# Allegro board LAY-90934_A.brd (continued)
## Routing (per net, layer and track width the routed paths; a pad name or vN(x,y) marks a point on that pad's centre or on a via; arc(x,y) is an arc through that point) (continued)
GND_CHASSIS: length 21.1
  TOP w0.635: J9.SH1 81.67,14.22 C174.2 R361.2
  BOTTOM w0.635: J9.SH2 J9.SH1
VBUS1_DET_3V3: length 10.5
  TOP w0.086: 90.93,57.91 90.99,57.86 90.99,56.73 90.99,56.73 90.99,56.58 U1.B3
  TOP w0.254: 90.93,57.91 90.93,59.06 88.01,61.98 85.23,61.98 R113.1
VBUS_DBG: length 14.7
  TOP w0.254: J11.A9 15.73,6.02 J11.B4 ; L13.1 10.83,8.55 TVS3.2 12.1,8.38 12.57,8.38 13.23,7.73 J11.A4 13.23,6.02 J11.B9
  BOTTOM w0.381: J11.B4 16.26,6.55 16.26,8.51 15.62,9.14 13.84,9.14 13.28,8.58 J11.B9
VBUS_IN: length 8
  TOP w0.254: U45.A1 U45.B1 U45.C1 U45.D1 ; U39.23 v1(46.76,25.27)
  TOP w0.381: R283.1 v1(44.45,25.01)
  L3_PWR w0.381: v1(44.45,25.01) 44.71,25.27 v1(46.76,25.27) 48.28,23.75 v3(48.89,23.75)
  vias: v3(48.89,22.86) v3(49.66,23.75) v3(49.66,22.86)
VBUS_OVLO_TH: length 3.4
  TOP w0.086: U45.B3 66.79,19.94 v1(67.56,20.71) R311.1 R313.2
VBUS_USB_DBG: length 7.3
  TOP w0.381: U50.3 10.5,13.55 v1(10.54,13.59) C177.1 C184.1 C189.1 ; U50.1 11.21,11.65 C189.1 ; C189.1 11.3,11.05 10.67,10.41 L13.2
VCC_ANA_1V8: length 9.3
  TOP w0.254: v2(93.23,54.86) 93.21,54.83 U1.E6 ; v2(93.19,50.84) 93.21,50.83 U1.N8 ; U1.L12 v2(95.73,52.32) ; U1.F12 v2(95.26,54.33)
  L2_GND w0.203: v2(95.26,54.33) 95.26,53.33 95.73,52.86 v2(95.73,52.32)
  L2_GND w0.254: v2(93.19,50.84) 94.41,50.84 94.74,51.18 94.74,51.69 95.37,52.32 v2(95.73,52.32)
  BOTTOM w0.254: C145.1 95.83,54.37 95.3,54.37 v2(95.26,54.33) ; C146.1 95.74,52.32 v2(95.73,52.32) ; v2(93.23,54.86) 93.25,54.88 C144.1
  vias: v1(31.24,44.58) v1(31.5,45.21) v1(32.13,44.58) v1(32.51,45.21) v1(33.02,44.58)
VCC_FT_1V8: length 26.8
  TOP w0.254: U28.64 4.32,29.02 v1(4.25,29.08) ; v1(12.83,37.34) 12.8,37.37 U28.37 ; U28.12 12.8,28.29 v1(12.83,28.32)
  BOTTOM w0.381: C261.1 10.72,36.58 L15.1 ; C261.1 12.86,37.31 v1(12.83,37.34) ; C261.1 12.86,29.12 C287.1 ; C287.1 C290.1 v1(4.25,29.08) ; C287.1 v1(12.83,28.32)
VCC_FT_3V3: length 257.7
  TOP w0.254: R112.1 v1(28.57,62.48) ; R252.2 v1(20.69,33.66) R255.2 ; U28.56 v1(6.35,33.02) ; U18.8 16.5,49.42 C67.1 ; v1(15.56,30.48) 15.59,30.52 U28.20 ; v1(5.01,18.16) 5.01,17.59 R333.1 ; v1(17.34,45.72) 17.39,45.66 U21.2 ; v1(4.19,36.2) 4.37,36.02 U28.50 ; R219.2 v1(12.19,44.19) ; U17.15 28.25,58.24 v1(27.94,58.55) ; v1(4.32,45.85) R198.1 ; C64.1 19.74,49.35 U21.15 ; R86.1 v1(42.42,66.68) ; R103.1 v1(28.57,63.5) ; R60.1 v1(38.73,69.6) ; U28.42 v1(10.3,37.22) ; C50.1 45.9,61.41 U16.15 ; v1(4.32,43.05) R221.1 ; v1(2.67,18.16) 2.42,18.16 2.17,17.91 R332.1 ; R282.1 v1(15.61,25.4) ; v1(4.32,51.44) R172.1 ; v1(4.32,48.64) R187.1 ; v1(15.75,35.94) 15.82,36.02 U28.31 ; R154.1 v1(14.35,55.37) ; R206.1 v1(13.58,44.45) ; C46.1 41.4,64.39 U14.6 ; R296.1 v1(4.32,24) ; U13.21 v1(41.15,70.1) ; R226.2 v1(10.66,41.54) ; R38.1 v1(38.73,72.64)
  TOP w0.381: v1(52.07,72.77) 54.1,72.77 55.37,71.5 55.37,70.23 v1(56.13,69.47) ; U17.2 25.09,55.32 C58.1 v1(25.02,54.48) ; C52.1 v1(27.94,58.55) ; C64.1 v1(18.67,49.66) ; 10.16,15.37 v1(9.14,15.37) ; v1(36.32,28.83) v1(34.55,28.83) 33.66,28.83 v1(32.26,30.23) 32.26,31.88 33.2,32.82 v1(34.04,32.82) ; v1(47.51,70.49) 47.5,70.5 C31.1 ; U16.2 42.74,58.62 C54.1 v1(42.67,57.79) ; R115.2 v1(43.31,62.61) ; U42.6 v1(5.01,18.16) ; v1(50.55,73.91) 50.55,84.33 50.93,84.71 v1(81.03,84.71) ; v1(62.74,61.21) 62.55,61.02 58.74,61.02 57.78,61.98 v1(50.04,61.98) ; v1(5.05,12.45) C188.1 5.08,11.65 U50.5 ; D18.A v1(22.73,35.56) ; TP160.1 v1(5.84,14.48) ; R180.2 v1(18.67,50.54) ; v1(17.27,48.39) C71.1 C67.1 v1(17.27,49.4) ; R195.2 v1(14.99,47.37) ; R120.2 v1(41.15,60.58) ; v1(41.02,63.75) C46.1 ; R145.2 v1(23.5,57.28) ; v1(44.83,61.72) C50.1 ; R124.2 v1(26.92,60.83)
  BOTTOM w0.203: U60.2 56.44,69.78 v1(56.13,69.47) ; U63.3 63.05,61.52 v1(62.74,61.21)
  BOTTOM w0.254: v1(50.55,65.09) R414.1 ; U64.15 36.5,30.57 36.32,30.39 C284.1 ; R413.1 v1(51.56,65.09) ; v1(5.01,18.16) 4.48,17.62 3.2,17.62 v1(2.67,18.16) ; U61.8 52.06,72.76 v1(52.07,72.77) ; U64.2 v1(34.04,32.82) ; U65.1 20.07,28.91 v1(20.07,28.45) ; R415.1 v1(52.58,65.09) ; U62.8 v1(47.51,70.49)
  BOTTOM w0.381: v1(5.01,18.16) 5.01,18.86 C311.1 ; C225.1 C229.1 41.15,70.1 v1(41.15,70.1) ; v1(56.13,69.47) C230.1 C231.1 ; v1(20.07,28.45) C299.1 C300.1 ; v1(10.3,37.22) 10.29,37.24 C258.1 ; C223.1 52.07,73.79 v1(52.07,72.77) ; v1(21.91,33.02) 26.42,33.02 27.18,32.26 30.35,32.26 31.74,30.87 R464.2 v1(32.26,30.23) ; v1(15.61,25.4) 14.98,24.77 L16.1 12.83,25.09 v1(12.83,25.53) ; v1(15.75,35.94) C263.1 ; v1(17.34,45.72) 17.46,45.85 C240.1 ; U68.5 132.6,47.1 132.08,47.63 C318.1 132.08,50.29 131.7,50.67 128.14,50.67 127.32,51.5 127.32,58.86 127.95,59.5 127.95,63.06 132.27,67.37 132.27,73.98 124.84,81.41 102.87,81.41 99.57,84.71 v1(81.03,84.71) ; v1(34.04,32.82) 33.96,32.89 C272.1 ; C282.1 v1(15.56,30.48) ; 4.95,36.32 4.32,36.32 v1(4.19,36.2) ; C236.1 C235.1 v1(62.74,61.21) ; R470.2 v1(34.55,28.83) ; L17.1 5.09,24.77 v1(4.32,24) ; v1(6.35,33.02) 6.35,33.02 C273.1 ; v1(36.32,28.83) C284.1
VCCO_5V: length 3.7
  TOP w0.254: U39.21 v1(47.76,25.4)
  BOTTOM w0.254: R472.1 C304.1 47.12,24.76 v1(47.76,25.4)
VDD_1P8: length 101.5
  TOP w0.203: v1(54.36,58.93) 54.17,59.12 51.75,59.12 R132.1 ; v1(44.96,41.4) 44.96,42.16 45.46,42.67 U23.29 ; R182.1 v1(21.46,51.18) ; 37.59,45.21 37.02,45.78 37.02,46.42 36.58,46.86 31.12,46.86 29.65,48.32 29.65,49.47 R184.1 ; TP131.1 65.15,32.13 65.72,32.7 65.72,33.59 66.55,34.42 66.55,41.47 v1(66.36,41.66) ; R200.1 v1(25.91,45.85)
  BOTTOM w0.203: v1(21.46,51.18) 21.84,50.8 23.62,50.8 27.81,46.61 27.81,43.94 30.23,41.53 36.83,41.53 v1(37.34,41.02) ; v1(25.91,45.85) 25.78,45.72 25.78,41.66 28.7,38.74 37.21,38.74 37.91,38.04 v1(38.86,38.04) ; v1(54.36,58.93) 54.55,59.12 57.85,59.12 62.74,54.23 62.74,43.69 63.75,42.67 66.04,42.67 66.55,42.16 66.55,41.85 v1(66.36,41.66) ; v1(44.96,41.4) 44.07,40.51 39.24,40.51 v1(38.61,41.15)
  vias: v1(38.61,37.19) v1(39.37,37.19) v1(63.5,29.97) v1(64.07,30.23)
VDD_1V8: length 196.7
  TOP w0.203: v1(67.12,41.66) 66.93,41.47 66.93,34.23 66.1,33.4 66.1,32.7 66.67,32.13 TP132.1 ; v1(54.36,59.69) 54.17,59.5 51.75,59.5 R127.1
  TOP w0.254: U20.8 120.02,50.93 v1(119.89,51.05) ; R386.1 v1(136.27,2.55) R387.1 ; U44.1 137.18,19.01 v1(137.1,18.92) C167.1 ; R327.1 v1(123.32,17.78) ; v2(109.76,39.5) U25.M4 U25.N4 ; U41.1 121.59,19.99 v1(121.41,19.81) ; v1(104.52,43.56) 104.43,43.66 R223.1 ; R233.1 120.02,39.31 v1(119.82,39.12) ; U25.P3 109.26,37.88 v1(108.84,37.47) ; R345.2 v1(121.28,17.78) R325.1 ; R239.1 v1(104.14,38.36) ; R34.1 74.3,74.8 v1(74.55,75.06) ; R326.1 v1(122.3,17.78) ; R257.1 v1(74.68,30.23) ; R328.1 v1(124.33,17.78) ; U43.1 v1(128.94,18.29) ; U25.P5 v1(110.26,37.47) ; R258.1 v1(78.49,31.5) ; R91.1 v1(85.22,69.72) ; U25.C6 v2(110.74,43.05)
  TOP w0.381: v1(80.39,75.18) 80.39,73.41 79.35,72.36 J5.1 v1(80.39,70.21) ; U34.5 v1(71.99,30.23) ; R300.1 74.55,21.84 73.15,23.24 v1(73.15,26.42) ; D20.A v1(66.29,27.05)
  BOTTOM w0.203: v1(67.12,41.66) 66.93,41.85 66.93,42.42 66.29,43.05 63.95,43.05 63.12,43.88 63.12,54.48 58.12,59.48 54.56,59.48 v1(54.36,59.69)
  BOTTOM w0.254: v1(74.68,30.23) 77.22,30.23 v1(78.49,31.5) ; v1(108.84,37.47) 108.95,37.58 C260.1 ; v1(110.62,36.45) 117.16,36.45 v1(119.82,39.12) 118.99,39.95 C238.1 119.13,50.17 C237.1 v1(119.89,51.05) ; 21.84,28.96 U65.11 ; C259.1 110.35,37.56 v1(110.26,37.47) ; v2(110.74,43.05) 110.76,43.07 C245.1 111.25,43.56 112.01,42.8 112.01,41.02 110.49,39.5 v2(109.76,39.5)
  BOTTOM w0.381: C310.1 129.03,18.38 v1(128.94,18.29) ; v1(141.1,9.65) 141.1,5.84 137.8,2.55 v1(136.27,2.55) ; v1(66.29,27.05) 65.15,25.91 51.31,25.91 50.1,27.11 24.32,27.11 23.75,27.69 C297.1 C298.1 21.84,28.96 ; v1(85.22,69.72) 84.73,70.21 v1(80.39,70.21) ; v1(121.41,19.81) 121.41,20.32 C308.1 ; R458.1 90.42,37.72 90.93,38.23 96.39,38.23 98.68,35.94 v1(98.68,29.72) 98.68,29.47 R471.1 ; C255.1 v2(109.76,39.5) ; v1(71.99,30.23) 72.01,30.21 C286.1
  vias: v1(67.82,30.23) v1(68.45,29.91) v1(69.09,30.23)
VDD_3P3: length 35.7
  TOP w0.203: 35.56,50.17 35.56,54.1 34.16,55.5 R152.1 ; v1(44.58,46.61) 45.32,45.87 U23.21 ; TP57.1 41.34,52.01 41.34,53.28 34.29,60.33 30.11,60.33 R126.1 ; R161.1 34.42,53.84 34.42,50.17 TP69.1
  BOTTOM w0.203: v1(44.58,46.61) 44.58,47.5 44.2,47.88 v1(39.62,47.88)
VDD_3V3: length 294.2
  TOP w0.203: TP56.1 36.5,50.85 36.21,50.85 35.94,51.12 35.94,54.35 R149.1 ; U27.14 v1(79.25,35.63) ; R52.1 v1(130.68,70.1) ; U49.3 v1(71.25,15.88) ; U23.32 46.99,41.13 46.56,40.7 v1(46.23,40.7) C87.2 ; U48.3 v1(31.5,13.21)
  TOP w0.254: v1(100.58,67.56) R88.1 R87.1 ; R375.1 v1(69.22,10.92) ; R274.1 96.45,26.48 L11.1 ; U10.14 v1(97.16,71.19) ; v1(121.54,22.61) 121.63,22.52 U41.11 ; R293.1 v1(124.33,24.7) ; v1(89.28,36.07) 89.53,35.82 R249.1 ; R203.1 v1(131.95,45.72) R202.1 ; U25.E6 v2(110.76,42.04) ; U25.K9 112.26,39.64 v2(112.39,39.5) ; U25.J10 113.12,40.53 v2(113.26,40.39) ; R76.1 v1(28.33,67.69) ; U44.11 137.63,20.99 v1(137.54,21.08) ; R30.1 v1(66.55,74.49) ; R306.1 v1(100.71,22.73) ; U43.11 v1(128.99,21.21) ; R331.1 R330.1 v1(32,19.69) ; R32.1 v1(68.58,74.49) ; R196.1 v1(128.28,46.48) ; R163.1 v1(109.98,53.98) ; U15.31 v1(113.28,61.23) ; R25.1 v1(102.49,73.66) ; v2(109.73,42.16) 109.87,42.03 U25.F5 ; 102.94,70.99 U11.A1 ; R81.1 v1(15.49,65.82) ; U29.14 v1(112.32,30.1) ; R27.1 v1(63.25,74.49) ; R292.1 v1(123.32,24.7) ; v1(93.09,73.72) 93.15,73.66 R22.1 ; R63.2 R67.2 R90.2 R97.2 139.19,64.64 138.94,64.39 v1(130.56,64.39) ; R382.1 v1(64.77,6.1) v1(64.77,9.4) R373.1 ; U40.15 v1(104.14,19.96) ; U9.14 v1(114.17,71.57) ; R291.1 v1(122.3,24.7) ; U30.14 v1(116.77,30.1) ; U31.14 v1(127.18,30.1) ; R29.1 v1(65.28,74.49) ; v1(125.54,61.98) R117.1 ; R290.1 v1(121.28,24.7) ; R256.1 v1(72.52,33.02) ; U15.27 v1(113.28,63.23) ; v1(120.65,72.01) R40.1 R48.1 ; v1(103.44,66.99) R94.1 R93.1 ; R84.1 v1(18.54,65.82) ; R37.1 v1(79.12,73.65)
  TOP w0.381: D30.A v1(13.72,15.37) ; R42.1 v1(104.52,71.88) ; v1(116.77,30.1) 116.77,29.41 C117.1 C120.1 ; v1(137.54,25.15) 138.06,25.15 R276.1 ; v1(62.61,68.45) 62.61,62.36 v1(63.75,61.21) ; C158.1 137.16,21.46 v1(137.54,21.08) ; v1(104.14,19.96) 103.62,19.96 C161.1 ; C114.1 C113.1 112.32,29.41 v1(112.32,30.1) ; v1(26.16,29.15) 26.16,26.8 v1(27.31,25.65) R280.1 ; C29.1 v1(62.23,74.55) J3.2 J3.1 ; U53.5 v1(8.4,10.05) ; v1(126.87,70.36) C37.1 C40.1 ; v1(10.29,79.76) C4.1 10.27,80.53 U3.5 ; R20.1 v1(17.78,75.82) ; C43.1 25.4,67.63 v1(25.27,67.75) U8.5 ; 102.94,70.99 C33.1 C34.1 v1(105.85,70.99) ; C35.1 C32.1 96.47,71.19 v1(97.16,71.19)
  TOP w0.508: L11.1 v1(96.45,24.89)
  L3_PWR w0.381: v1(89.28,36.07) 89.03,35.81 79.43,35.81 v1(79.25,35.63)
  BOTTOM w0.203: U59.14 126.93,70.41 v1(126.87,70.36) ; v1(63.75,61.21) 63.45,61.52 U63.2 ; U60.3 56.32,70.18 v1(56.13,70.36)
  BOTTOM w0.254: C269.1 78.49,33.91 77.6,33.02 v1(72.52,33.02) ; v1(131.95,45.72) 129.03,45.72 v1(128.28,46.48) ; R430.1 113.81,61.23 v1(113.28,61.23) ; R467.1 v1(123.95,30.1) ; 52.71,5.46 R478.2 51.25,3.37 10.1,3.37 8.13,5.33 8.13,9.78 v1(8.4,10.05) ; 52.71,5.46 64.14,5.46 v1(64.77,6.1) ; 52.71,5.46 R477.1 ; C256.1 112.41,39.48 v2(112.39,39.5) ; R408.1 100.84,67.82 v1(100.58,67.56) ; R405.1 v1(103.89,67.5) ; R434.1 R433.1 v1(111.75,60.83) ; v2(110.76,42.04) 110.86,41.94 C251.1 ; R402.2 v1(56.39,74.04)
  BOTTOM w0.381: L18.2 v1(108.02,25.27) ; C232.1 113.44,63.25 113.42,63.23 v1(113.28,63.23) ; v1(63.75,61.21) C234.1 C233.1 ; v1(10.41,77.34) 8.13,77.34 v1(6.73,75.95) ; v1(27.31,25.65) 27.31,22.98 28.45,21.84 29.85,21.84 v1(32,19.69) 30.35,18.03 30.35,14.35 30.73,13.97 C315.1 31.53,13.24 v1(31.5,13.21) ; C224.1 C226.1 114.1,71.5 v1(114.17,71.57) ; C269.1 C267.1 78.56,35.63 v1(79.25,35.63) ; C314.1 71.21,15.84 v1(71.25,15.88) ; v1(8.4,10.05) 8.41,10.03 C316.1 12.45,10.03 13.72,11.3 v1(13.72,15.37) ; v1(128.99,21.21) 129.03,21.17 C309.1 ; v1(127.18,30.1) 127.18,29.39 C288.1 C289.1 ; C252.1 113.35,40.29 v2(113.26,40.39) ; v1(121.54,22.61) 121.67,22.48 C307.1 ; C227.1 C228.1 56.01,70.49 v1(56.13,70.36) ; v1(46.23,40.7) 45.53,40.01 38.23,40.01 37.85,40.39 v1(28.19,40.39)
  BOTTOM w0.508: L14.1 v1(89.28,36.07) 89.28,37.59 90.55,38.86 96.77,38.86 99.44,36.2 v1(99.44,25.27)
  vias: v1(36.96,52.45) v1(38.1,52.45) v1(39.24,52.45) v1(108.84,25.27) v1(109.86,25.27) v1(110.74,25.27) v1(111.76,35.18) v1(111.76,34.29) v1(112.52,35.18)
VDD_5V: length 77.1
  TOP w0.203: C192.2 71.65,11.54 U49.12
  TOP w0.254: U48.12 31.1,17.29 v1(30.99,17.4)
  TOP w0.381: R289.1 v1(35.43,24) 36.58,22.86 v1(36.58,13.21) ; U36.5 32.35,25.02 v1(33.15,25.02) C127.1 ; J2.1 38.62,79.74 ; J2.1 38.62,81.55 ; J2.1 36.82,79.74 ; J2.1 36.82,81.55 ; C15.1 C18.1 26.54,76.07 v1(26.54,75.5) U8.3 ; 34.8,80.26 34.8,80.76 ; 34.8,80.26 35.29,80.26 ; 34.8,80.26 34.8,79.77 ; 34.8,78.99 35.29,78.99 ; 34.8,78.99 34.8,79.49 ; 34.8,78.99 34.8,78.5 ; v1(64.26,7.56) 60.9,7.56 58.29,4.95 ; C192.2 v1(72.9,11.05)
  BOTTOM w0.254: R479.1 v1(56.9,3.3)
  BOTTOM w0.381: v1(72.9,11.05) 70.23,11.05 66.74,7.56 v1(64.26,7.56) ; v1(26.54,75.5) 26.54,77.72 28.45,79.63 35.81,79.63 ; v1(36.58,13.21) v1(36.58,6.22) ; v1(33.15,25.02) 34.42,25.02 v1(35.43,24) 34.04,22.61 34.04,19.56 C312.2 v1(30.99,17.4)
  vias: v1(56.26,4.83) v1(56.9,4.19) v1(85.47,82.42) v1(86.74,82.17) v1(86.74,81.53)
VDD_ANA_0P8: length 13.6
  BOTTOM w0.203: R459.1 42.35,33.97 53.66,33.97 53.97,34.29 53.97,34.99 v1(53.47,35.5)
VDD_ANA_0V8: length 23.7
  TOP w0.254: v2(96.39,53.85) 96.23,54.01 U1.F13 ; v2(96.21,51.81) 96.23,51.79 U1.M13 ; U1.C4 v2(91.24,55.83)
  L3_PWR w0.254: v2(91.24,55.83) 91.79,56.39 92.46,56.39 92.71,56.13 92.71,54.1 92.96,53.85 v2(96.39,53.85)
  L3_PWR w0.381: 96.46,52.32 96.21,52.08 v2(96.21,51.81)
  BOTTOM w0.203: v1(53.47,34.51) 53.31,34.35 42.35,34.35 R450.1
  BOTTOM w0.254: C133.1 91.19,55.88 v2(91.24,55.83) ; C132.1 99.07,48.53 v1(99.19,48.64) ; C130.1 96.51,53.96 v2(96.39,53.85) ; v2(96.21,51.81) 96.28,51.74 C131.1
  vias: v1(52.07,33.02) v1(53.09,33.02)
VDD_ANA_1V8: length 11.1
  TOP w0.203: R183.1 29.27,49.47 29.27,48.17 30.96,46.48 36.32,46.48 36.64,46.16 36.64,45.78 36.07,45.21
VDD_COIN_3V: length 23.6
  TOP w0.381: v1(10.79,67.82) 11.68,68.71 R46.2 R47.1
  TOP w0.508: BT1.2 8.72,67.82 8.72,67.82 v1(10.79,67.82) 10.79,59.06 10.16,58.42 5.84,58.42
VDD_RTC_3V3: length 5.9
  TOP w0.254: C24.1 v1(15.75,73.53) 16.28,73.01 U12.15
  TOP w0.381: R19.2 13.95,74.3 C23.1 14.5,74.3 C24.1
VDD_SNVS_0V8: length 1.5
  TOP w0.254: v2(95.23,55.88) 95.19,55.83 U1.C10
  BOTTOM w0.254: C102.1 95.24,56.31 95.23,56.31 v2(95.23,55.88)
VDD_SOC: length 63.6
  TOP w0.254: v1(54.74,36.58) R242.2
  BOTTOM w0.203: v1(62.23,35.43) 61.91,35.12 61.91,33.85 60.01,31.94 42.35,31.94 R461.1 ; v1(63.88,37.97) 63.37,37.47 63.37,33.15 60.13,29.91 42.35,29.91 R469.1
  BOTTOM w0.254: C107.1 95.3,52.84 v2(95.25,52.79) C106.1 ; v1(62.23,36.7) 62.1,36.58 v1(54.74,36.58) ; C110.1 93.26,52.79 v2(93.22,52.83) 93.22,53.26 C111.1 ; v1(94.07,43.19) C109.1 ; v1(95.42,43.19) C105.1
  BOTTOM w0.381: C104.1 94.66,53.65 v2(94.74,53.09) ; v2(93.74,52.58) C108.1
  vias: v1(63.88,37.08) v1(63.88,36.07) v1(64.77,37.72) v1(64.77,36.83) v1(64.77,35.94) v2(93.73,53.09)
VDD_SOC_0V85: length 21.8
  BOTTOM w0.203: R460.1 42.35,32.32 59.75,32.32 61.53,34.1 61.53,35.12 v1(61.21,35.43)
VDD_SOC_SW: length 3.8
  TOP w0.254: U24.5 58.69,43.23 v1(58.58,43.34) 58.42,43.5 TP85.1 59.22,44.2 59.23,44.2 R214.2 R215.2
VDD_USB_3V3: length 85.5
  TOP w0.203: TP68.1 33.97,50.22 33.97,53.28 R165.1
  TOP w0.254: U1.E8 94.18,54.83 v2(94.21,54.86)
  L3_PWR w0.381: v1(60.13,66.04) 58.29,66.04 57.28,65.02 57.28,56.39 53.97,53.09 43.81,53.09 42.29,51.56 35.56,51.56 v1(32.89,48.9)
  BOTTOM w0.254: v1(60.13,66.04) 61.15,67.06 69.34,67.06 70.23,66.17 82.55,66.17 83.19,65.53 85.6,65.53 94.36,56.77 94.36,55.82 94.74,55.44 C155.1 94.23,54.88 v2(94.21,54.86)
VDD_VBAT_3V: length 3.2
  TOP w0.254: U12.16 15.7,72.01 v1(14.48,72.01) C30.1
  TOP w0.381: C30.1 12.83,72.01 R47.2
VEN_SPI_CS/1V8: length 4.6
  TOP w0.086: J8.64 123.29,14.88 123.06,15.11 v1(122.18,15.11) 121.28,16.01 R345.1 121.15,16 R344.1
VINT: length 1.7
  TOP w0.203: U23.36 48.59,40.21 C89.1
ADC0: length 8.3
  TOP w0.086: R98.1 v1(80.9,65.02) 79.35,65.02 ; J5.4 77.34,64.14 77.6,63.88 79.12,63.88 79.35,64.11 79.35,65.02 ; 79.35,65.02 J5.2
ADC1: length 14.3
  TOP w0.086: J5.8 73.3,64.16 73.56,63.91 75.08,63.91 75.31,64.14 J5.6 75.31,67.82 75.63,68.14 v1(81.03,68.14) 81.09,68.07 R65.1
ADC_GND: length 2.7
  TOP w0.086: J5.7 v1(73.3,72.26) 73.3,72.88 R33.1
ADC_HIGH: length 3.7
  TOP w0.086: J5.3 v1(77.34,72.26) R36.1 R37.2
ADC_IN0: length 31.2
  TOP w0.086: U1.B8 93.48,56.58 93.48,61.2 92.96,61.72 92.96,68.58 92.84,68.71 92.84,71.37 92.2,72.01 86.11,72.01 84.2,70.1 84.2,66.68 v1(83.57,66.04) C45.1 R98.2
ADC_IN1: length 30.3
  TOP w0.086: R65.2 C44.1 v1(83.57,67.06) 83.95,67.44 83.95,70.23 85.98,72.26 92.33,72.26 93.09,71.5 93.09,68.83 93.22,68.71 93.22,61.85 93.73,61.33 U1.A8
ADC_LOW: length 3.7
  TOP w0.086: R34.2 R35.1 v1(75.31,72.26) J5.5
AUD_NMUTE: length 49.4
  TOP w0.086: v1(105.85,34.16) 105.54,34.16 100.84,29.46 100.84,24.13 101.09,23.88 102.62,23.88 103,23.5 103,22.1 103.12,21.98 R308.1 103.89,21.98 104.48,22.57 U40.11 ; R139.2 v1(115.19,56.39)
  BOTTOM w0.086: v1(115.19,56.39) 115.7,55.88 115.7,49.4 114.94,48.64 109.35,48.64 105.85,45.15 v1(105.85,34.16)
BT_MODE0: length 1.8
  BOTTOM w0.086: R431.2 61.34,61.98 61.34,62.23 61.65,62.54 U63.6
BT_MODE1: length 1.4
  BOTTOM w0.086: R429.2 61.29,62.94 U63.7
BT_MODE2: length 1.3
  BOTTOM w0.086: R428.2 61,63.34 U63.8
BT_MODE3: length 2.5
  BOTTOM w0.086: U63.9 62.65,63.72 v1(61.85,64.52) R427.2
BUF_POR: length 58.6
  TOP w0.086: v1(83.44,42.48) 80.84,42.48 73.27,34.92 R256.2 73.29,32.24 U34.4 ; R118.1 v1(110.24,60.83)
  BOTTOM w0.086: v1(110.24,60.83) 109.09,59.68 109.09,50.51 102.02,43.43 98.42,43.43 97.73,44.13 91,44.13 89.53,42.67 83.63,42.67 v1(83.44,42.48)
BYPASS1: length 1.7
  TOP w0.086: U48.4 31.9,13.44 32,13.34 32,12.83 32.38,12.45
CAN1_RX: length 83.2
  TOP w0.086: R15.1 TP4.1 v1(28.19,78.11) ; U10.1 98.46,69.76 v1(98.17,69.47)
  BOTTOM w0.086: v1(98.17,69.47) 98.04,69.34 96.65,69.34 95.88,70.1 95.88,71.25 94.61,72.52 92.58,72.52 91.95,73.15 85.85,73.15 84.58,71.88 79.5,71.88 78.87,71.25 73.28,71.25 72.9,71.63 71.37,71.63 70.87,71.12 61.98,71.12 61.47,71.63 61.47,74.68 60.58,75.57 31.5,75.57 28.96,78.11 v1(28.19,78.11)
CAN1_TX: length 83.3
  TOP w0.086: U10.8 101.06,71.59 v1(101.09,71.63) ; R16.1 TP5.1 v1(29.97,78.11)
  BOTTOM w0.086: v1(101.09,71.63) 99.57,71.63 97.54,69.6 96.77,69.6 96.14,70.23 96.14,71.37 94.74,72.77 92.71,72.77 92.08,73.41 85.72,73.41 84.45,72.14 79.38,72.14 78.74,71.5 73.41,71.5 73.02,71.88 71.25,71.88 70.74,71.37 62.1,71.37 61.72,71.76 61.72,74.8 60.71,75.82 31.62,75.82 29.97,77.47 v1(29.97,78.11)
CAN_H: length 16.8
  TOP w0.254: R43.2 C27.2 33.01,73.66 L3.2 ; J2.2 40.51,79.85 40.51,77.47 38.99,75.95 34.23,75.95 D2.1 33.35,73.94 L3.2 ; L3.2 33.52,73.15 L4.3
CAN_L: length 15.5
  TOP w0.254: L3.3 35.23,73.94 D2.2 35.6,75.44 39.24,75.44 41.02,77.22 41.02,79.95 J2.3 ; L3.3 35.06,73.15 L4.2 ; L3.3 35.57,73.66 C28.1 R44.1
CAN_RX: length 1.8
  TOP w0.254: U8.4 v1(25.27,75.5) R15.2
CAN_STBY: length 88.9
  TOP w0.086: v1(99.95,69.47) 99.66,69.76 U10.4 ; v1(30.61,75.57) 29.97,74.93 29.97,67.56 29.46,67.06 R76.2 29.08,68.92 U8.8
  BOTTOM w0.086: v1(99.95,69.47) 99.06,69.47 98.55,68.96 96.65,68.96 95.63,69.98 95.63,71.12 94.49,72.26 92.46,72.26 91.82,72.9 85.98,72.9 84.71,71.63 79.63,71.63 78.99,70.99 73.15,70.99 72.77,71.37 71.5,71.37 70.99,70.87 61.85,70.87 61.21,71.5 61.21,74.55 60.45,75.31 30.86,75.31 v1(30.61,75.57)
CAN_TX: length 1.8
  TOP w0.254: U8.1 v1(29.08,75.5) R16.2
CANH: length 13.8
  TOP w0.254: L4.4 33.52,70.1 L3.1 33.88,69.63 34.06,69.45 34.06,66.7 33.66,66.29 27.81,66.29 27.56,66.55 27.56,67.69 27.81,67.95 U8.7
CANL: length 15.6
  TOP w0.254: L4.1 35.06,70.1 L3.4 34.7,69.63 34.52,69.45 34.52,66.53 33.78,65.79 27.56,65.79 27.05,66.29 27.05,67.44 26.54,67.95 U8.6
CLKIN1: length 16.8
  TOP w0.086: U1.A6 92.73,60.81 92.2,61.34 92.2,67.06 91.57,67.69 88.27,67.69 TP20.1 R54.1
CLKIN2: length 18.2
  TOP w0.086: U1.B6 92.48,56.58 92.48,60.68 91.95,61.21 91.95,66.8 91.44,67.31 87.38,67.31 TP19.1 R53.1
CLKO01: length 2.2
  TOP w0.086: R224.2 TP104.1
CON_JTAG_NRST: length 18.7
  TOP w0.086: v1(70.87,25.02) D22.C D23.C ; J7.10 80.52,30.99 v1(80.89,31.36) R259.2
  BOTTOM w0.086: v1(80.89,31.36) 74.55,25.02 v1(70.87,25.02)
DAC_BCLK: length 2.7
  TOP w0.086: U40.9 104.91,23.87 v1(104.01,24.76) R278.2
DAC_DAT: length 1.9
  TOP w0.086: R297.2 v1(112.65,22.99) 112.42,23.22 U40.7
DAC_LRCLK: length 1.8
  TOP w0.086: U40.8 112.51,23.87 v1(112.65,24) R287.2
DAC_MCLK: length 2.5
  TOP w0.086: R285.2 v1(104.2,23.56) 104.54,23.22 U40.10
DBG_ACC: length 1.8
  TOP w0.086: TP154.1 32.52,17.02 32.3,16.79 U48.9
DCDC_5V: length 32.1
  TOP w0.203: 30.48,30.61 31.5,31.62 31.5,34.42 25.91,40.01 21.6,40.01 R232.1
  TOP w0.254: U58.3 54.74,7.36 v1(54.61,7.49) ; U47.G3 U47.F3 U47.E3 U47.D3 ; U47.D2 U47.E2 U47.F2 U47.G2 ; 44.32,22.35 U39.28
  TOP w0.381: v1(25.4,25.91) TP145.1 C124.1 24.44,27.24 U33.3 24.44,29.53 24.13,29.85 22.86,29.85 22.55,29.53 U33.1 ; R277.1 143.26,26.29 ; 43.81,22.86 43.81,22.86 44.32,22.35
  BOTTOM w0.381: v1(54.61,7.49) 53.97,8.13 C317.1
  vias: v1(19.81,18.42) v1(20.83,18.42) v1(21.84,18.42) v1(22.86,18.42) v1(23.37,19.81) v1(29.21,29.08) v1(29.34,29.72) v1(29.46,30.61) v1(29.85,28.77) v1(30.35,29.21) v1(40.26,22.73) v1(40.51,22.1) v1(41.02,22.73) v1(41.02,21.59) v1(41.66,22.1) v1(49.4,11.56) v1(49.91,11.05) v1(50.42,11.56) v1(50.93,11.05) v1(51.43,11.56) v1(56.39,7.37) v1(56.9,8.64) v1(56.9,7.87) v1(143.13,28.96) v1(143.13,27.94) v1(143.64,28.45) v1(144.15,29.85) v1(144.15,28.96) v1(144.15,27.94)
DMIC_PDM_CLK: length 34.8
  TOP w0.086: v1(97.79,72.39) 99.44,72.39 99.66,72.17 U10.9 ; v1(97.79,73.91) 97.79,84.2 97.16,84.84 81.75,84.84 80.1,83.19 U66.2 TP1.1
  BOTTOM w0.086: v1(97.79,73.91) v1(97.79,72.39)
DMIC_PDM_DATA0: length 165.9
  TOP w0.086: U53.4 8.68,8.75 8,9.42 TP161.1 8,16.76 6.29,18.48 v1(6.29,20.7) ; v1(53.28,62.61) 52.96,62.93 52.96,63.37 52.2,64.14 49.4,64.14 49.15,64.39 42.8,64.39 38.73,60.33 37.85,60.33 35.62,62.55 v1(35.24,62.55) ; U10.16 97.57,70.39 96.65,69.47 94.49,69.47 94.23,69.72 94.23,71.37 92.2,73.41 84.2,73.41 83.69,72.9 83.69,68.07 v1(83.44,67.82)
  BOTTOM w0.086: v1(6.29,20.7) 4.83,20.7 3.24,22.29 3.24,37.02 6.22,40.01 6.22,53.28 13.97,61.02 13.97,66.04 14.73,66.8 30.99,66.8 v1(35.24,62.55) ; v1(53.28,62.61) 53.09,62.8 53.09,63.37 54.86,65.15 58.17,65.15 60.71,67.69 83.31,67.69 v1(83.44,67.82)
DMIC_PDM_DATA1: length 104
  TOP w0.086: U10.3 v1(99.26,68.99) ; TP2.1 8.08,79.5 8.35,79.23 U3.4 9.92,79.23 v1(10.41,78.74)
  BOTTOM w0.086: v1(99.26,68.99) 98.98,68.71 96.52,68.71 95.38,69.85 95.38,70.99 94.36,72.01 92.33,72.01 91.69,72.64 86.11,72.64 84.84,71.37 79.76,71.37 79.12,70.74 73.02,70.74 72.64,71.12 71.63,71.12 71.12,70.61 61.72,70.61 60.96,71.37 60.96,74.42 60.32,75.06 25.02,75.06 21.34,78.74 v1(10.41,78.74)
DRAM_CA0_A: length 23.1
  TOP w0.086: U2.H2 79.45,54.91 79.55,55 79.55,55.13 79.39,55.28 79.39,55.41 79.6,55.63 79.6,56.54 79.71,56.65 80.78,56.65 80.89,56.76 80.89,57.69 80.98,57.79 81.11,57.79 81.2,57.69 81.2,57.14 81.29,57.04 81.48,57.04 81.57,57.14 81.57,57.69 81.66,57.79 81.84,57.79 81.93,57.69 81.93,57.14 82.03,57.04 82.21,57.04 82.3,57.14 82.3,57.69 82.39,57.79 82.57,57.79 82.67,57.69 82.67,57.31 TP36.1 82.94,57.17 83.03,57.26 83.03,57.69 83.12,57.79 83.31,57.79 83.4,57.69 83.4,57.16 83.52,57.04 83.67,57.04 83.76,57.14 83.76,57.69 83.86,57.79 84.04,57.79 84.13,57.69 84.13,57.23 86.76,54.61 86.91,54.61 87.02,54.71 87.02,54.84 86.51,55.35 86.51,55.48 86.77,55.75 86.94,55.75 87.04,55.65 87.04,55.36 87.2,55.19 87.33,55.19 87.45,55.07 87.45,54.92 87.59,54.78 87.96,54.78 88.06,54.68 88.78,54.68 88.88,54.59 88.88,54.44 88.94,54.38 89.14,54.38 89.2,54.43 89.2,54.62 89.25,54.68 89.47,54.68 89.53,54.61 89.53,54.47 89.63,54.38 89.78,54.38 89.82,54.33 U1.F1
DRAM_CA1_A: length 21.1
  TOP w0.086: U1.E2 90.73,54.96 90.61,55.08 90.13,55.08 90.11,55.1 88.29,55.1 85.04,58.35 80.38,58.35 80.29,58.26 80.29,57.75 80.23,57.68 79.81,57.68 78.93,56.8 78.8,56.8 78.73,56.87 78.73,57 79.52,57.79 79.52,57.88 79.45,57.95 79.32,57.95 78.43,57.07 78.43,56.83 78.31,56.71 77.64,56.71 77.55,56.62 77.55,56.46 77.61,56.39 78.13,56.39 78.22,56.3 78.22,55.02 78.34,54.91 U2.J2
DRAM_CA2_A: length 34.1
  TOP w0.086: U1.D2 90.48,55.58 89.81,55.58 89.59,55.81 89.35,55.81 89.26,55.9 89.26,56.12 89.16,56.21 89,56.21 88.83,56.38 88.83,56.56 88.67,56.73 88.48,56.73 88.31,56.9 88.31,57.05 88.22,57.15 86.93,57.15 84.98,59.1 79.24,59.1 78.87,58.73 78.87,58.6 79,58.47 79,58.35 78.87,58.22 78.74,58.22 78.61,58.35 78.48,58.35 78.35,58.22 78.35,58.09 78.48,57.96 78.48,57.83 78.35,57.7 78.22,57.7 78.11,57.81 77.98,57.81 77.85,57.68 77.85,57.55 77.96,57.44 77.96,57.31 77.83,57.18 77.7,57.18 77.59,57.3 77.46,57.3 77.05,56.88 77.05,53.93 77.33,53.65 77.33,53.45 77.04,53.16 77.04,52.6 77.13,52.51 77.34,52.51 77.42,52.44 77.42,52.31 77.34,52.23 77.13,52.23 77.03,52.14 77.03,52.01 77.13,51.92 77.38,51.92 77.47,51.83 77.47,51.55 77.56,51.46 77.73,51.46 77.82,51.55 77.82,51.81 77.91,51.91 78.07,51.91 78.15,51.82 78.15,51.55 78.24,51.46 78.5,51.46 78.59,51.55 78.59,52.14 78.71,52.26 78.92,52.26 79.01,52.17 79.01,51.91 79.1,51.82 79.28,51.82 79.38,51.93 79.38,52.18 79.47,52.28 79.74,52.28 79.83,52.18 79.83,51.93 79.94,51.82 80.67,51.82 80.89,51.6 80.89,51.22 80.64,50.97 79.8,50.97 79.64,50.81 79.64,50.34 79.56,50.26 79.56,50 79.4,49.84 79.4,49.74 79.56,49.58 79.56,49.4 79.47,49.31 U2.H9
DRAM_CA3_A: length 32.9
  TOP w0.086: U1.C1 89.95,55.83 88.4,57.39 87.04,57.39 85.08,59.35 79.15,59.35 78.89,59.09 78.76,59.09 78.66,59.19 78.53,59.19 78.4,59.06 78.4,58.93 78.5,58.83 78.5,58.7 78.37,58.57 78.24,58.57 78.14,58.67 78.01,58.67 77.88,58.54 77.88,58.41 77.98,58.31 77.98,58.18 77.86,58.05 77.73,58.05 77.65,58.13 77.52,58.13 77.39,58 77.39,57.87 77.47,57.79 77.47,57.66 77.34,57.53 77.27,57.53 77.1,57.7 76.97,57.7 76.84,57.57 76.84,57.44 76.99,57.3 76.99,57.17 76.83,57.02 76.83,51.78 77.4,51.22 78.55,51.22 78.94,51.6 80.34,51.6 80.43,51.51 80.43,51.3 80.34,51.21 79.61,51.21 79.46,51.05 79.05,51.05 78.96,51.15 78.83,51.15 78.61,50.93 78.61,50.52 78.87,50.26 78.87,50.03 78.99,49.91 78.99,49.5 78.92,49.43 78.92,49.2 78.74,49.02 78.74,48.89 78.87,48.77 79,48.77 79.23,49 79.42,49 79.51,48.91 79.51,48.78 U2.H10
DRAM_CA4_A: length 33
  TOP w0.086: U2.H11 79.21,47.73 79.21,48.05 79.13,48.13 77.86,48.13 76.96,49.04 76.96,49.91 76.83,50.04 76.83,50.17 76.96,50.29 76.96,50.46 76.8,50.62 76.68,50.62 76.56,50.5 76.43,50.5 76.3,50.63 76.3,50.76 76.42,50.88 76.42,51.01 76.29,51.14 76.16,51.14 76.04,51.02 75.91,51.02 75.79,51.15 75.79,51.28 75.92,51.42 75.92,51.55 75.79,51.68 75.67,51.68 75.53,51.54 75.4,51.54 75.27,51.67 75.27,51.8 75.36,51.89 75.36,52.06 75,52.43 75,55.82 75.25,56.07 75.25,56.26 74.99,56.52 74.99,56.71 78.61,60.33 88.05,60.33 89.52,58.86 89.52,58.29 90.37,57.44 90.37,57.14 90.48,57.03 90.48,56.48 90.64,56.33 U1.B2
DRAM_CA5_A: length 31.7
  TOP w0.086: U2.J11 78.31,47.43 77.57,47.43 76.71,48.28 76.71,49.82 74.97,51.56 74.89,51.56 74.36,52.1 74.36,56.38 78.52,60.54 88.14,60.54 89.77,58.9 89.77,58.41 90.58,57.6 90.58,57.29 90.73,57.14 U1.A2
DRAM_CK_C_A: length 26.5
  TOP w0.094: U2.J9 78.59,49.38 v2(78.26,49.71) 77.88,49.71 77.65,49.94 77.65,50.23 76.28,51.6 76.28,57.61 78.61,59.94 85.32,59.94 87.35,57.9 88.59,57.9 90.17,56.33 U1.B1
  BOTTOM w0.094: R205.2 77.7,49.71 v2(78.26,49.71)
DRAM_CK_T_A: length 26.6
  TOP w0.086: U1.C2 90.79,55.89 90.79,56 90.71,56.08 90.13,56.08 90.08,56.13
  TOP w0.094: 90.08,56.13 88.51,57.7 87.27,57.7 85.23,59.74 78.7,59.74 76.48,57.52 76.48,51.69 77.42,50.75 77.72,50.75 77.85,50.88 78.17,50.88 78.26,50.78 v2(78.26,50.51) 78.26,50.26 78.42,50.11 U2.J8
  BOTTOM w0.094: v2(78.26,50.51) 77.69,50.51 R205.1
DRAM_CKE0_A: length 18.7
  TOP w0.086: v2(78.26,52.91) 78.59,53.23 U2.J4 ; U1.G1 89.74,53.83 89.64,53.93 87.68,53.93 v2(87.24,54.37)
  BOTTOM w0.086: v2(78.26,52.91) 78.35,53 R207.2 78.61,53.85 78.61,55.43 78.18,55.87 78.18,56.49 78.97,57.28 85.13,57.28 87.24,55.16 v2(87.24,54.37)
DRAM_CKE1_A: length 19.3
  TOP w0.086: v2(88.49,54.3) 88.65,54.14 89.75,54.14 89.81,54.08 90.48,54.08 U1.F2 ; v2(78.25,52.18) 78.58,52.51 U2.J5
  BOTTOM w0.086: v2(88.49,54.3) 88.49,54.3 88.11,53.92 87.05,53.92 85.31,55.66 85.31,56.11 84.42,57 79.48,57 78.92,56.44 78.92,52.24 R208.2 78.86,52.18 v2(78.25,52.18)
DRAM_DATA0_A: length 12.4
  TOP w0.086: U1.L2 90.48,51.58 88.72,51.58 88.02,50.88 87.28,50.88 86.46,51.69 85.85,51.69 TP60.1 85.59,51.44 81.35,51.44 80.83,51.96 80.83,53.01 U2.F4
DRAM_DATA1_A: length 10.6
  TOP w0.086: U2.E4 81.5,52.99 81.5,52.29 82.06,51.74 84.25,51.74 84.8,52.29 85.26,52.29 TP54.1 85.62,52.22 88.37,52.22 88.76,51.83 90.23,51.83 U1.L1
DRAM_DATA2_A: length 8.9
  TOP w0.086: U1.K2 90.48,52.08 88.86,52.08 88.51,52.44 85.64,52.44 85.37,52.71 TP51.1 84.62,52.92 82.87,52.92 U2.C4
DRAM_DATA3_A: length 8
  TOP w0.086: U2.B4 83.14,53.62 83.25,53.74 84.44,53.74 85.09,53.09 TP49.1 85.91,52.65 88.65,52.65 88.97,52.33 U1.K1
DRAM_DATA4_A: length 8.3
  TOP w0.086: U1.J1 89.18,52.83 88.94,53.08 86.5,53.08 85.22,54.36 TP47.1 84.94,54.36 83.96,55.34 83.57,55.34 U2.B2
DRAM_DATA5_A: length 10.6
  TOP w0.086: U2.C2 82.79,55.21 82.79,55.96 82.93,56.1 83.92,56.1 84.29,55.73 84.29,55.53 TP45.1 84.97,54.99 86.67,53.29 89.08,53.29 89.28,53.08 90.48,53.08 U1.H2
DRAM_DATA6_A: length 11.5
  TOP w0.086: U1.H1 89.39,53.33 89.22,53.5 86.82,53.5 85.33,54.99 85.33,55.13 TP39.1 84.01,56.45 81.97,56.45 81.48,55.96 81.48,55.21 U2.E2
DRAM_DATA7_A: length 13.1
  TOP w0.086: U1.G2 90.48,53.58 89.67,53.58 89.54,53.72 87.13,53.72 TP43.1 85.72,55.27 84.26,56.74 81.2,56.74 80.86,56.4 80.86,55.23 U2.F2
DRAM_DATA8_A: length 12.6
  TOP w0.076: U2.E11 81.19,47.78 v3(81.51,48.11)
  TOP w0.086: U2.E11 81.48,47.41 81.48,46.65 82.06,46.08 85.06,46.08 86.74,47.75 88.68,47.75 90.01,49.08 90.48,49.08 U1.T2
DRAM_DATA9_A: length 14.3
  TOP w0.076: U2.F11 80.54,47.78 v3(80.86,48.11)
  TOP w0.086: U1.U2 90.73,48.76 89.41,47.43 89.41,46.67 88.07,45.34 86.11,45.34 85.85,45.59 81.54,45.59 80.83,46.3 80.83,47.41 U2.F11
DRAM_DATA10_A: length 9.8
  TOP w0.086: U2.C11 82.79,47.41 82.79,46.71 82.93,46.56 84.92,46.56 TP77.1 85.09,46.61 86.49,48.01 88.52,48.01 89.84,49.33 U1.T1
DRAM_DATA11_A: length 8.8
  TOP w0.086: U1.R2 90.48,49.58 89.66,49.58 88.35,48.27 86.24,48.27 85.28,47.31 TP73.1 83.54,47.31 U2.B11
DRAM_DATA12_A: length 8.4
  TOP w0.086: U2.C9 82.92,49.74 84.92,49.74 TP67.1 85.31,50.13 88.23,50.13 88.87,50.78 89.88,50.78 89.93,50.83 U1.N1
DRAM_DATA13_A: length 8.5
  TOP w0.086: U1.N2 90.48,50.58 89.99,50.58 89.94,50.54 88.95,50.54 88.3,49.89 86.72,49.89 86.14,49.31 85.13,49.31 TP72.1 84.75,48.93 83.51,48.93 U2.B9
DRAM_DATA14_A: length 11.3
  TOP w0.086: U2.E9 81.5,49.63 81.5,50.52 81.89,50.9 84.61,50.9 TP65.1 85.13,50.38 88.16,50.38 88.82,51.04 89.61,51.04 89.65,51.08 90.48,51.08 U1.M2
DRAM_DATA15_A: length 11.7
  TOP w0.086: U1.M1 88.79,51.33 88.09,50.63 85.77,50.63 TP64.1 85.25,51.15 81.12,51.15 80.83,50.86 80.83,49.61 U2.F9
DRAM_DMI0_A: length 9.4
  TOP w0.086: U1.J2 90.48,52.58 89.85,52.58 89.84,52.59 89.06,52.59 88.79,52.86 86.23,52.86 85.37,53.72 TP48.1 84.71,54.1 84.71,54.23 84.41,54.53 82.91,54.53 U2.C3
DRAM_DMI1_A: length 8.6
  TOP w0.086: U1.R1 89.49,49.83 88.19,48.53 85.87,48.53 85.47,48.14 82.86,48.14 U2.C10
DRAM_NCS0_A: length 27
  TOP w0.086: U1.D1 89.73,55.33 89.49,55.56 89.32,55.56 89.09,55.33 88.51,55.33 87.53,56.31 87.53,56.45 87.65,56.57 87.83,56.57 88.78,55.62 88.93,55.62 89.02,55.71 89.02,55.83 87.97,56.88 87.63,56.88 87.39,56.64 87.09,56.64 84.93,58.8 84.8,58.8 84.65,58.65 84.52,58.65 84.35,58.81 84.12,58.81 84.03,58.72 84.03,58.68 83.94,58.59 83.75,58.59 83.66,58.68 83.66,58.72 83.57,58.81 83.39,58.81 83.3,58.72 83.3,58.68 83.21,58.59 83.02,58.59 82.93,58.68 82.93,58.72 82.84,58.81 82.66,58.81 82.57,58.72 82.57,58.68 82.47,58.59 82.29,58.59 82.2,58.68 82.2,58.72 82.11,58.81 81.93,58.81 81.83,58.72 81.83,58.68 81.74,58.59 81.56,58.59 81.47,58.68 81.47,58.72 81.38,58.81 81.19,58.81 81.1,58.72 81.1,58.68 81.01,58.59 80.83,58.59 80.74,58.68 80.74,58.72 80.65,58.81 80.46,58.81 80.37,58.72 80.37,58.68 80.28,58.59 80.1,58.59 80.01,58.68 80.01,58.72 79.91,58.81 79.59,58.81 79.5,58.72 TP35.1 79.5,58.5 78.19,57.19 78.19,57.03 78.1,56.94 77.45,56.94 77.26,56.75 77.26,54.08 77.66,53.67 78.69,53.67 78.87,53.49 78.87,53.05 79,52.92 79.13,52.92 79.18,52.96 79.18,53.25 U2.H4
DRAM_NCS1_A: length 27.7
  TOP w0.086: U1.E1 90.23,54.7 90.14,54.61 89.88,54.61 89.79,54.7 89.79,54.8 89.7,54.89 88.15,54.89 87.01,56.03 86.7,56.03 86.27,55.61 86.14,55.61 86.05,55.7 86.05,55.83 86.54,56.32 86.54,56.45 86.45,56.54 86.32,56.54 85.8,56.02 85.67,56.02 85.58,56.11 85.58,56.24 86.08,56.74 86.08,56.87 85.99,56.96 85.86,56.96 85.43,56.53 85.3,56.53 85.19,56.63 85.19,56.76 85.63,57.19 85.63,57.32 85.54,57.41 85.41,57.41 84.95,56.95 84.79,56.95 84.74,57 84.74,57.13 85.22,57.61 85.22,57.69 85.12,57.78 85,57.78 84.55,57.32 84.42,57.32 84.37,57.37 84.37,57.71 84.44,57.77 84.58,57.77 84.69,57.88 84.69,58.01 84.6,58.11 83.84,58.11 83.72,57.99 83.49,57.99 83.48,57.99 83.37,58.11 83.07,58.11 82.93,57.97 82.74,57.97 82.6,58.11 82.32,58.11 82.2,57.98 82.09,57.98 81.96,58.11 81.61,58.11 81.45,57.95 81.29,57.95 81.14,58.11 80.65,58.11 80.56,58.01 80.56,57.88 80.65,57.79 80.65,57.64 80.53,57.52 80.53,57.39 80.65,57.28 80.65,56.97 80.56,56.89 80.05,56.89 79.96,56.98 79.96,57.11 79.99,57.15 80.15,57.15 80.24,57.24 80.24,57.35 80.15,57.44 79.91,57.44 79.64,57.17 79.64,56.94 79.55,56.84 79.32,56.84 78.92,56.45 78.92,55.64 78.71,55.43 78.71,55.3 78.89,55.11 78.89,54.82 78.7,54.64 78.7,54.46 78.8,54.37 78.97,54.37 79.22,54.63 79.62,54.63 79.71,54.54 79.71,54.4 79.61,54.29 79.31,54.29 79.24,54.22 U2.H3
DRAM_NRESET: length 38.4
  TOP w0.086: v1(90.3,58.55) 90.3,58.93 88.39,60.83 78,60.83 73.68,56.51 73.68,55.53 73.53,55.38 72.71,55.38 72.39,55.06 72.39,52.23 73.66,50.96 73.66,48.09 U2.T11 74.36,47.38 v2(74.36,47.31) ; v2(91.73,54.83) 91.73,54.33 U1.F4
  BOTTOM w0.086: v2(91.73,54.83) 91.63,54.93 91.63,57.21 v1(90.3,58.55) ; R102.1 77.25,47.31 77.24,47.31 R201.1 74.37,47.31 v2(74.36,47.31)
DRAM_SDQS0_C_A: length 13.1
  TOP w0.094: U1.K4 v2(91.73,52.83) ; U2.E3 81.51,53.78 v2(81.51,53.71)
  BOTTOM w0.094: v2(91.73,52.83) 91.37,52.47 88.25,52.47 87.81,52.91 86.57,52.91 84.67,54.82 82.17,54.82 81.66,54.3 81.66,53.85 v2(81.51,53.71)
DRAM_SDQS0_T_A: length 12.9
  TOP w0.094: U1.M4 v2(91.73,51.83) ; U2.D3 82.16,53.78 v2(82.16,53.71)
  BOTTOM w0.094: v2(91.73,51.83) 91.73,51.88 91.35,52.26 88.16,52.26 87.72,52.71 86.49,52.71 84.58,54.61 82.26,54.61 81.86,54.22 81.86,53.9 82.05,53.71 v2(82.16,53.71)
DRAM_SDQS1_C_A: length 11.4
  TOP w0.086: 90.04,50.08 90.05,50.08 90.48,50.08 U1.P2
  TOP w0.094: U2.E10 81.19,48.58 v2(81.51,48.91) ; v2(87.87,48.9) 88.04,49.07 88.25,49.07 89.25,50.08 90.04,50.08
  BOTTOM w0.094: v2(81.51,48.91) 81.63,48.79 81.63,48.52 82.37,47.78 85.66,47.78 86.19,48.31 87.17,48.31 87.76,48.9 v2(87.87,48.9)
DRAM_SDQS1_T_A: length 11.3
  TOP w0.094: U1.P1 90.19,50.29 89.17,50.29 88.16,49.28 v2(87.34,49.28) ; U2.D10 81.84,48.58 v2(82.16,48.91)
  BOTTOM w0.094: v2(82.16,48.91) 81.96,48.91 81.84,48.79 81.84,48.6 81.95,48.49 82.22,48.49 82.35,48.35 82.35,48.09 82.46,47.98 85.58,47.98 86.11,48.51 87.08,48.51 87.48,48.91 87.48,49.14 v2(87.34,49.28)
DRAM_ZN: length 3.1
  TOP w0.086: v2(91.73,53.79) U1.H4
  BOTTOM w0.086: R204.1 89.92,53.09 90.93,53.09 91.64,53.79 v2(91.73,53.79)
DRAM_ZQ0: length 1
  TOP w0.086: U2.A5 84.11,52.18 v2(84.11,52.11)
  BOTTOM w0.086: v2(84.11,52.11) 84.11,51.65 R209.2
DRAM_ZQ1: length 1
  TOP w0.086: U2.A8 84.11,50.43 v2(84.11,50.51)
  BOTTOM w0.086: v2(84.11,50.51) 84.09,50.53 R211.1
EE_CLK: length 3.8
  TOP w0.086: TP158.1 2.91,15.37 R342.1 R332.2 3.11,17.73 U42.4
EE_CS: length 3.8
  TOP w0.086: U42.5 4.06,18.42 4.2,18.28 R333.2 R343.1 4.2,15.37 TP159.1
EE_DATA: length 4.4
  TOP w0.086: R281.2 TP147.1 2.92,24.39 2.91,24.38 R295.1 3.11,23.17 U42.3
EMMC_VDDIM: length 2.3
  TOP w0.086: U25.C2 108.51,43.28 v2(107.82,43.28)
  BOTTOM w0.254: v2(107.82,43.28) 107.36,43.28 C247.1 C244.1
EN_SNK: length 15.8
  TOP w0.086: v1(21.27,17.34) 20.99,17.06 U47.F1 ; v1(31.62,11.81) 31.38,11.56 R370.2
  BOTTOM w0.086: v1(31.62,11.81) 31.38,11.56 26.16,11.56 22.99,14.73 22.99,16.64 22.29,17.34 v1(21.27,17.34)
EN_SRC: length 13.9
  TOP w0.086: v1(20.7,17.78) 20.63,17.78 U47.G1 ; R369.2 29.46,11.56 29.27,11.75 v1(29.27,12.07)
  BOTTOM w0.086: v1(20.7,17.78) 22.23,17.78 23.24,16.76 23.24,14.86 26.29,11.81 29.02,11.81 v1(29.27,12.07)
ENET1_MDC: length 26.3
  TOP w0.086: TP143.1 v1(96.52,28.07) R267.1 ; v1(97.54,34.67) 97.54,36.83 92.84,41.53 92.84,43.57 93.48,44.22 93.48,49.08 U1.T8
  BOTTOM w0.086: v1(97.54,34.67) 97.09,34.23 97.09,30.54 96.01,29.46 96.01,28.58 v1(96.52,28.07)
ENET1_MDIO: length 24.4
  TOP w0.086: R263.1 v1(96.52,29.08) TP140.1 ; U1.U7 93.23,44.31 92.58,43.66 92.58,41.28 97.09,36.77 97.09,34.35 v1(97.54,33.91)
  BOTTOM w0.086: v1(97.54,33.91) 97.54,33.9 R471.2 v1(96.52,29.08)
ENET1_NINT: length 59.9
  TOP w0.086: v1(102.17,62.8) 101.66,62.8 98.68,59.82 98.68,57.79 97.99,57.09 97.99,56.73 97.84,56.58 97.63,56.58 97.49,56.44 97.49,55.73 97.34,55.58 96.98,55.58 U1.D14 ; v1(89.73,44.83) 89.73,43.75 89.28,43.31 89.28,36.83 88.78,36.33 R249.2 88.78,35.15 88.27,34.64 88.27,31.24 88.37,31.14 U35.31
  BOTTOM w0.086: v1(89.73,44.83) 90.61,45.72 98.04,45.72 99.06,44.7 101.09,44.7 107.19,50.8 107.19,58.04 102.43,62.8 v1(102.17,62.8)
ENET1_NRST: length 59
  TOP w0.086: v1(122.55,65.53) R95.2 ; U35.12 94.24,27.94 R274.2 95.13,27.44 95.25,27.56 97.03,27.56 TP144.1 106.17,35.18 v1(106.55,35.18)
  BOTTOM w0.086: v1(122.55,65.53) 122.55,65.02 117.47,59.94 117.47,56.52 115.95,54.99 115.95,49.28 115.06,48.39 109.47,48.39 106.11,45.02 106.11,35.62 v1(106.55,35.18)
ENET1_RD0: length 21.2
  TOP w0.086: U35.25 91.26,32.33 91.44,32.51 91.44,33.53 93.09,35.18 v1(93.47,35.18) 93.98,35.69 93.98,37.85 91.57,40.26 91.57,44.32 TP83.1 92.23,44.99 U1.U5
  BOTTOM w0.086: R446.2 v1(93.47,35.18) R455.1
ENET1_RD1: length 22.2
  TOP w0.086: U1.T6 92.48,49.08 92.48,44.59 91.82,43.93 91.82,40.51 94.49,37.85 v1(94.49,35.18) 93.98,34.67 93.09,34.67 91.82,33.4 91.82,32.38 91.66,32.22 U35.24
  BOTTOM w0.086: R454.1 v1(94.49,35.18) R445.2
ENET1_RD2: length 22.5
  TOP w0.086: U1.U6 92.73,44.5 92.08,43.84 92.08,40.77 95.5,37.34 v1(95.5,35.18) 94.68,34.35 93.28,34.35 92.2,33.27 92.2,32.39 92.06,32.24 U35.23
  BOTTOM w0.086: R444.2 v1(95.5,35.18) R453.1
ENET1_RD3: length 24
  TOP w0.086: U1.T7 92.99,49.08 92.99,44.41 92.33,43.75 92.33,41.02 96.52,36.83 v1(96.52,35.18) 95.38,34.04 93.47,34.04 92.58,33.15 92.58,32.39 92.46,32.26 U35.22
  BOTTOM w0.086: R452.1 v1(96.52,35.18) R443.2
ENET1_RX_CTL: length 20.8
  TOP w0.086: U35.26 90.86,32.31 91.06,32.51 91.06,33.78 v1(92.46,35.18) 93.34,36.07 93.34,37.97 91.33,39.99 91.33,42.91 TP89.1 91.06,44.45 91.98,45.38 91.98,49.08 U1.T5
  BOTTOM w0.086: R456.1 v1(92.46,35.18)
ENET1_RXC: length 23.7
  TOP w0.086: U35.27 90.46,32.29 90.68,32.51 90.68,34.42 v1(91.44,35.18) 91.95,35.69 92.5,35.69 92.58,35.77 92.58,35.98 92.5,36.07 92.03,36.07 91.95,36.15 91.95,36.36 92.03,36.45 92.84,36.45 92.96,36.58 92.96,37.85 91.06,39.75 91.06,42.55 90.55,43.05 TP84.1 91.73,45.51 U1.U4
  BOTTOM w0.086: R457.1 v1(91.44,35.18) C262.1 R447.2
ENET1_TD0: length 25.3
  TOP w0.086: U1.U9 94.23,43.94 93.6,43.31 93.6,42.29 98.93,36.96 98.93,32.26 98.17,31.5 95.88,31.5 TP137.1 94.49,30.73 94.09,30.34 U35.18
ENET1_TD1: length 26.5
  TOP w0.086: U1.R9 94.48,49.58 94.48,41.91 99.31,37.08 99.31,32.13 97.41,30.23 94.49,30.23 94.2,29.94 U35.17
ENET1_TD2: length 26.1
  TOP w0.086: U1.U10 94.73,42.17 99.69,37.21 99.69,32 97.6,29.91 94.68,29.91 94.31,29.54 U35.16
ENET1_TD3: length 27.4
  TOP w0.086: U1.T10 94.99,49.08 94.99,42.43 100.08,37.34 100.08,31.88 97.79,29.59 94.87,29.59 94.42,29.14 U35.15
ENET1_TX_CTL: length 25.2
  TOP w0.086: U35.19 93.98,30.74 94.49,31.24 95.12,31.24 95.88,32 TP134.1 98.17,32 98.55,32.39 98.55,36.83 93.34,42.04 93.34,43.4 93.98,44.03 93.98,49.08 U1.T9
ENET1_TXC: length 25.9
  TOP w0.086: U35.20 93.88,31.14 94.36,31.62 94.74,31.62 TP133.1 95.12,33.31 95.21,33.4 95.41,33.4 95.5,33.31 95.5,32.34 95.59,32.26 95.8,32.26 95.88,32.34 95.88,33.27 96.01,33.4 97.79,33.4 98.04,33.66 98.04,36.83 93.09,41.78 93.09,43.49 93.73,44.13 U1.U8
ETH1_10/100M_LINK/ACTIVE: length 23.8
  TOP w0.086: R305.1 84.45,15.49 89.15,10.8 89.15,8.13 92.47,4.81 J9.13
ETH1_1000M_LINK/ACTIVE: length 21.6
  TOP w0.086: R303.1 R304.1 83.44,15.24 88.39,10.29 88.39,8.14 J9.11
ETH1_AVDD1V0: length 12.6
  TOP w0.203: U35.38 87.52,28.34 v1(87.5,28.32) ; U35.3 v1(90.06,25.91) ; U35.8 v1(92.06,25.84)
  BOTTOM w0.381: C296.1 90.04,25.92 v1(90.06,25.91) ; v1(92.06,25.84) 92.08,25.86 C295.1 ; C291.1 87.63,28.45 v1(87.5,28.32)
  BOTTOM w0.508: R468.2 88.25,29.45 C285.1 C291.1 88.27,27.8 89.39,26.67 C296.1 C295.1
ETH1_AVDD3V3: length 12.6
  TOP w0.203: U35.40 88.47,27.54 88.27,27.33 v1(88.27,25.78) ; v1(93.6,26.04) 93.6,27.46 U35.11
  TOP w0.508: L11.2 93.85,25.78 v1(93.6,26.04)
  BOTTOM w0.381: v1(88.27,25.78) C301.1
  BOTTOM w0.508: v1(88.27,25.78) 88.9,25.15 92.71,25.15 v1(93.6,26.04) C294.1
ETH1_CLK125_OUT: length 2.1
  TOP w0.086: TP138.1 87.81,29.54 U35.35
ETH1_CT: length 4.1
  TOP w0.086: C148.1 J9.1
ETH1_DVDD1V0: length 4.2
  TOP w0.203: v1(93.09,32.77) 92.86,32.53 U35.21
  BOTTOM w0.381: v1(93.09,32.77) 93.09,32 95.24,32 R462.2
ETH1_DVDD3V3: length 27.8
  TOP w0.203: v1(89.41,32.77) 89.66,32.52 U35.29
  TOP w0.254: R253.1 84.45,34.04 v1(83.57,34.04) 81.53,32 81.53,23.62 R303.2 ; 86.87,36.32 v1(86.87,37.02)
  BOTTOM w0.254: v1(83.57,34.04) 86.55,37.02 v1(86.87,37.02) 87.88,36 87.88,34.42 88.52,33.78 89.23,33.78 L14.2
  BOTTOM w0.381: 88.27,32 89.28,32 89.41,32.13 v1(89.41,32.77) 89.41,33.6 L14.2
ETH1_LED0/CFG_EXT: length 20.9
  TOP w0.086: R305.2 v1(84.45,23.37) ; U35.32 88.13,30.74 87.88,30.99 R247.1 R246.2 v1(86.87,34.61)
  BOTTOM w0.086: v1(86.87,34.61) 86.55,34.93 85.72,34.93 85.34,34.54 85.34,24.26 v1(84.45,23.37)
ETH1_LED1/CFGLDO0: length 47.3
  TOP w0.086: v1(84.58,24.13) 84.96,23.75 84.96,15.62 89.53,11.05 89.53,8.38 91.82,6.1 97.04,6.1 J9.14 ; U35.33 88.09,30.34 87.5,30.92 87.5,33.91 87.25,34.16 86.61,34.16 86.36,34.42 86.36,34.8 C94.1 R245.1 v1(84.84,34.54)
  BOTTOM w0.086: v1(84.58,24.13) 85.03,24.57 85.03,34.35 v1(84.84,34.54)
ETH1_LED2/CFGLDO1: length 37.4
  TOP w0.086: U35.34 88.05,29.94 86.87,31.12 C95.1 R254.1 R253.2 84.45,32.64 v1(84.07,32.26) ; v1(83.95,24.13) 83.95,15.37 88.77,10.54 88.77,5.98 J9.12
  BOTTOM w0.086: v1(83.95,24.13) 84.71,24.89 84.71,32 84.45,32.26 v1(84.07,32.26)
ETH1_TRX0_N: length 13.1
  TOP w0.076: J9.3 88.52,16.89 88.32,16.7 87.77,16.7 87.38,17.09 87.38,19.94 87.89,20.45 87.89,21.27 88.02,21.4 U37.2 U37.9 88.02,23.3 87.89,23.44 87.89,23.75 89.58,25.44 89.58,26.25 89.66,26.33 U35.2
ETH1_TRX0_P: length 13.1
  TOP w0.076: J9.2 87.71,15.7 87.71,16.43 87.14,17 87.14,20.04 87.65,20.55 87.65,21.27 87.52,21.4 U37.1 U37.10 87.52,23.3 87.65,23.44 87.65,23.85 89.34,25.54 89.34,26.25 89.26,26.33 U35.1
ETH1_TRX1_N: length 13
  TOP w0.076: U35.5 90.86,26.33 90.78,26.25 90.78,25.12 89.39,23.73 89.39,23.44 89.52,23.3 U37.6 U37.5 89.52,21.4 89.39,21.27 89.39,20.55 89.92,20.02 89.92,17.09 90.31,16.7 90.86,16.7 91.06,16.89 J9.5
ETH1_TRX1_P: length 13
  TOP w0.076: J9.4 90.25,15.7 90.25,16.43 89.68,17 89.68,19.92 89.15,20.45 89.15,21.27 89.02,21.4 U37.4 U37.7 89.02,23.3 89.15,23.44 89.15,23.82 90.54,25.21 90.54,26.25 90.46,26.33 U35.4
ETH1_TRX2_N: length 12.9
  TOP w0.076: U35.7 91.66,26.33 91.58,26.25 91.58,25.34 92.97,23.95 92.97,23.44 93.1,23.3 U38.9 U38.2 93.1,21.4 92.97,21.27 92.97,20.45 92.46,19.94 92.46,17.09 92.78,16.76 93.47,16.76 93.6,16.89 J9.7
ETH1_TRX2_P: length 12.9
  TOP w0.076: J9.6 92.74,15.65 92.74,16.48 92.22,17 92.22,20.04 92.73,20.55 92.73,21.27 92.6,21.4 U38.1 U38.10 92.6,23.3 92.73,23.44 92.73,23.85 91.34,25.24 91.34,26.25 91.26,26.33 U35.6
ETH1_TRX3_N: length 13.1
  TOP w0.076: J9.9 96.14,16.89 95.94,16.7 95.39,16.7 95,17.09 95,20.02 94.47,20.55 94.47,21.27 94.6,21.4 U38.5 U38.6 94.6,23.3 94.47,23.44 94.47,23.85 92.78,25.54 92.78,26.25 92.86,26.33 U35.10
ETH1_TRX3_P: length 13.1
  TOP w0.076: 94.87,15.24 95.33,15.7 95.33,16.43 94.76,17 94.76,19.92 94.23,20.45 94.23,21.27 94.1,21.4 U38.4 U38.7 94.1,23.3 94.23,23.44 94.23,23.75 92.54,25.44 92.54,26.25 92.46,26.33 U35.9
ETH1_VDD1V0: length 28.4
  TOP w0.203: v1(88.77,32.64) 89.26,32.15 U35.30
  TOP w0.381: v1(96.33,30.85) 96.34,30.86 TP135.1
  BOTTOM w0.381: C275.1 86.83,32.04 C271.1 88.39,33.02 v1(88.77,32.64) ; R462.1 v1(96.33,30.85)
  BOTTOM w0.508: R462.1 95.38,25.91 93.85,24.38 87.76,24.38 85.98,26.16 85.98,30.23 86.5,30.75 R468.1 87.12,31.75 C275.1
ETH1_VDDIO: length 14.5
  TOP w0.203: v1(90.17,32.8) 90.06,32.69 U35.28
  TOP w0.381: v1(92.46,37.66) 90.17,35.37 v1(90.17,32.8)
  BOTTOM w0.254: v1(92.46,37.66) R447.1 R446.1 R445.1 R444.1 R443.1
  BOTTOM w0.381: C278.1 90.33,31.97 90.17,32.13 v1(90.17,32.8) 90.42,33.06 R458.2
ETH1_XTALI: length 6.2
  TOP w0.086: Y2.3 84.86,31.38 85.03,31.21 85.03,29.65 85.22,29.46 C112.1 86.73,29.46 R264.2 87.26,29.33 87.45,29.14 U35.36
ETH1_XTALO: length 7.2
  TOP w0.086: U35.37 87.02,28.74 R264.1 86.73,28.45 C121.1 83.19,28.45 82.39,29.25 Y2.1
EXP3V3_EN: length 40
  TOP w0.086: v1(104.77,73.47) v1(106.43,73.47) ; R5.1 v1(88.9,78.99) ; R70.2 v1(115.82,68.33)
  BOTTOM w0.086: v1(106.43,73.47) 104.46,75.44 94.23,75.44 90.68,78.99 v1(88.9,78.99) ; v1(115.82,68.33) 115.44,67.95 112.65,67.95 111.76,67.06 106.55,67.06 105.41,68.2 105.41,72.83 v1(104.77,73.47)
EXP5V_EN: length 80.1
  TOP w0.086: v1(128.52,64.45) 129.03,63.94 129.03,62.1 123.57,56.64 121.03,56.64 120.4,56.01 117.86,56.01 117.22,56.64 R141.2 ; R1.1 v1(84.96,84.07)
  BOTTOM w0.086: v1(84.96,84.07) 99.44,84.07 102.62,80.9 124.71,80.9 131.83,73.79 131.83,67.75 v1(128.52,64.45)
EXP_3V3:
  vias: v1(89.79,77.03)
EXP_5V:
  vias: v1(88.9,79.88)
EXP_GPIO_IO08: length 15.6
  TOP w0.086: U9.3 116.28,70.16 116.84,69.6 117.73,69.6 119.76,71.63 119.76,73.66 120.65,74.55 120.65,78.87 121.92,80.14 J4.24
EXP_GPIO_IO09: length 13
  TOP w0.086: U9.9 116.68,72.36 116.84,72.52 117.73,72.52 117.86,72.64 117.86,73.57 117.95,73.66 118.15,73.66 118.24,73.57 118.24,72.48 118.33,72.39 118.53,72.39 118.62,72.48 118.62,73.57 118.71,73.66 118.91,73.66 119,73.57 119,71.72 119.09,71.63 119.29,71.63 119.38,71.72 J4.21
EXP_GPIO_IO10: length 10.2
  TOP w0.086: J4.19 116.84,74.42 116.97,74.3 118.91,74.3 119,74.21 119,74 118.91,73.91 116.29,73.91 116.2,74 116.2,74.21 116.12,74.3 115.91,74.3 115.82,74.21 115.82,72.9 115.48,72.55 U9.12
EXP_GPIO_IO11: length 13.5
  TOP w0.086: J4.23 121.92,74.42 120.14,72.64 120.14,71.5 118.87,70.23 118.87,69.47 118.49,69.09 115.7,69.09 v1(114.87,69.92) U9.16
EXP_NIRQ: length 36.4
  TOP w0.086: U1.T4 91.48,49.08 91.48,45.98 v1(90.8,45.3) 90.04,44.54 90.04,43.3 R224.1 ; R135.1 v1(108.02,57.28)
  BOTTOM w0.086: v1(90.8,45.3) 98.08,45.3 98.93,44.45 101.22,44.45 107.44,50.67 107.44,56.71 v1(108.02,57.28)
EXP_SEL: length 4.1
  TOP w0.086: U9.15 114.35,71.17 114.18,71 R61.1 114.17,69.08 v1(114.17,68.39) R69.2
EXT1_PWREN: length 66.8
  TOP w0.086: R279.1 138.56,24.64 134.87,24.64 v1(130.68,28.83) ; v1(125.6,21.72) 125.48,21.59 125.48,17.14 R480.2 ; R101.2 125.35,64.01 v1(125.73,63.63)
  BOTTOM w0.086: v1(125.73,63.63) 125.98,63.37 125.98,61.72 125.35,61.09 125.35,57.28 124.71,56.64 124.71,50.93 126.24,49.4 126.24,38.23 130.43,34.04 130.43,29.08 v1(130.68,28.83) 131.13,28.38 131.13,27.24 v1(125.6,21.72)
FRS_EN: length 19.1
  TOP w0.086: U47.B6 v1(17.78,15.46) ; v1(29.31,10.1) 29.31,10.16 30.48,11.33 30.48,13.46 30.7,13.68 U48.1
  BOTTOM w0.086: v1(17.78,15.46) 17.78,14.86 19.18,13.46 22.35,13.46 25.53,10.29 29.12,10.29 v1(29.31,10.1)
FSC_CTRL_H1: length 36.8
  TOP w0.086: v1(60.71,45.59) R215.1
  BOTTOM w0.086: v1(60.71,45.59) 62.17,47.05 62.17,53.78 60.2,55.75 53.72,55.75 52.58,56.9 52.58,58.04 51.69,58.93 51.69,63.5 53.09,64.9 53.09,69.72 52.32,70.49 51.82,70.49 51.56,70.74 U61.7
FSC_CTRL_H2: length 25.5
  TOP w0.086: v1(51.18,53.72) 51.69,53.21 v1(51.69,50.04)
  BOTTOM w0.086: v1(51.69,50.04) 52.32,49.4 R435.1 ; U61.5 50.56,70.73 51.56,69.72 52.07,69.72 52.45,69.34 52.45,67.5 52.07,67.12 52.07,64.26 50.8,62.99 50.8,54.1 v1(51.18,53.72)
FT_BMODE_DIR: length 30
  TOP w0.086: v1(61.59,61.6) 59.69,63.5 59.69,70.61 57.09,73.22 45.15,73.22 44.69,72.76 U13.14
  BOTTOM w0.086: U63.4 62.62,62.14 U63.5 61.76,62.14 61.59,61.98 v1(61.59,61.6) 61.59,61.35 R432.1
FT_BOOT_MODE0: length 21.2
  TOP w0.086: U13.1 42.69,67.16 44.32,65.53 56.77,65.53 57.91,64.39 57.91,62.74 v1(58.93,61.72)
  BOTTOM w0.086: R431.1 59.18,61.47 v1(58.93,61.72)
FT_BOOT_MODE1: length 20
  TOP w0.086: U13.2 43.19,67.17 44.58,65.79 56.9,65.79 58.17,64.52 58.17,63.25 v1(58.93,62.48)
  BOTTOM w0.086: R429.1 v1(58.93,62.48)
FT_BOOT_MODE2: length 18.7
  TOP w0.086: v1(58.93,63.5) 58.42,64.01 58.42,64.64 57.02,66.04 44.83,66.04 43.69,67.18 U13.3
  BOTTOM w0.086: R428.1 v1(58.93,63.5)
FT_BOOT_MODE3: length 17.4
  TOP w0.086: v1(58.93,64.52) 57.15,66.29 45.09,66.29 44.19,67.19 U13.4
  BOTTOM w0.086: R427.1 v1(58.93,64.52)
FT_CTRL_H1: length 10.4
  TOP w0.086: v1(51.8,67.5) 50.85,66.55 45.34,66.55 44.69,67.2 U13.5
  BOTTOM w0.086: U61.1 52.06,67.75 v1(51.8,67.5) 51.56,67.26 R413.2
FT_CTRL_H2: length 8.7
  TOP w0.086: U13.6 45.19,67.2 45.59,66.8 50.11,66.8 v1(50.8,67.5)
  BOTTOM w0.086: R414.2 50.55,67.24 v1(50.8,67.5) 51.06,67.75 U61.3
FT_CTRL_H3: length 1.9
  TOP w0.086: TP18.1 46.72,68.6 U13.7
FT_EECLK: length 20.7
  TOP w0.086: R342.2 2.16,16.5 2.16,15.37 2.67,14.86 v1(3.68,14.86) 4.32,14.86 5.84,16.38 5.84,20.96 6.1,21.21 6.1,28.38 6.6,28.89 6.6,29.59 6.18,30.02 U28.62
FT_EECS: length 14.6
  TOP w0.086: R343.2 v1(5.43,17) 5.59,17.15 5.59,21.08 5.84,21.34 5.84,28.45 6.35,28.96 6.35,29.34 6.17,29.52 U28.63
FT_EEDATA: length 9
  TOP w0.086: R295.2 2.17,28.45 v1(4.19,30.48) 4.23,30.52 U28.61
FT_EXP_SCL: length 2.1
  TOP w0.086: R45.2 v1(40.77,71.63) 41.3,71.1 U13.19
FT_EXP_SDA: length 1.9
  TOP w0.086: R51.2 v1(40.77,70.61) 40.78,70.6 U13.20
FT_IO_NINT1: length 58.2
  TOP w0.086: R64.1 v1(38.61,68.58) 37.85,67.82 37.85,66.29 36.32,64.77 22.1,64.77 12.83,55.5 12.83,47.12 14.48,45.47 14.48,41.53 14.73,41.28 16.51,41.28 19.18,38.61 19.18,36.58 18.8,36.2 18.41,36.2 17.74,35.52 U28.30
